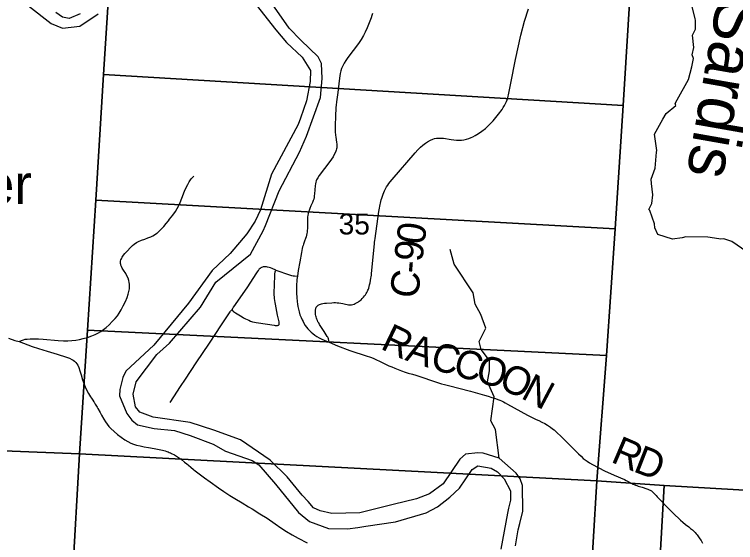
# Model space of a CAD drawing. Extents: x 396.2 to 468.4, y 232.6 to 279.1.
# Drawn here: x 421.615 to 423.054, y 274.071 to 275.126 of the extents above; entities that cross this region are included whole.
import ezdxf

# ---------------------------------------------------------------- set-up
doc = ezdxf.new("R2010")
doc.units = 0
for name, color, linetype in [('GM_X_County_Road', 7, 'Continuous'), ('GM_X_County_Road_Text', 7, 'Continuous'), ('GM_X_Major_River', 7, 'Continuous'), ('GM_X_Minor_River', 7, 'Continuous'), ('GM_X_Minor_River_Text', 7, 'Continuous'), ('GM_X_Section', 7, 'Continuous'), ('GM_X_Section_Text', 7, 'Continuous'), ('GM_X_Township_Road', 7, 'Continuous'), ('GM_X_Unincorporated_Text', 7, 'Continuous')]:
    doc.layers.add(name, color=color, linetype=linetype)

msp = doc.modelspace()

# ---------------------------------------------------------------- linework, layer by layer
at = {"layer": 'GM_X_County_Road'}
for points in [[(422.2429, 274.4712), (422.2422, 274.4755), (422.2419, 274.4771), (422.2416, 274.4784), (422.2411, 274.48), (422.2403, 274.4815), (422.2394, 274.483), (422.2329, 274.4926), (422.224, 274.5067), (422.2222, 274.5098), (422.2208, 274.5124), (422.2197, 274.5148), (422.2186, 274.5173), (422.2178, 274.5195), (422.2171, 274.522), (422.2165, 274.5244), (422.2161, 274.527), (422.2157, 274.5301), (422.2156, 274.533), (422.2156, 274.5349), (422.2159, 274.5367), (422.2162, 274.538), (422.2167, 274.5395), (422.2175, 274.5411), (422.2185, 274.5425), (422.2198, 274.5439), (422.2214, 274.5452), (422.2225, 274.5459), (422.2238, 274.5465), (422.2257, 274.5473), (422.2281, 274.548), (422.2306, 274.5486), (422.234, 274.5491), (422.2376, 274.5493), (422.2487, 274.5503), (422.2526, 274.5505), (422.2557, 274.5505), (422.259, 274.5503), (422.2626, 274.5499), (422.2665, 274.5492), (422.2706, 274.5484), (422.2756, 274.5474), (422.2789, 274.5468), (422.2819, 274.5463), (422.2849, 274.5461), (422.2874, 274.5463), (422.2903, 274.5467), (422.2928, 274.5475), (422.2951, 274.5484), (422.2978, 274.5497), (422.3001, 274.5511), (422.3017, 274.5523), (422.3032, 274.5534), (422.3047, 274.5546), (422.3067, 274.5563), (422.3087, 274.5584), (422.3115, 274.5612), (422.3137, 274.5637), (422.3154, 274.5659), (422.3171, 274.5684), (422.3185, 274.5709), (422.3195, 274.573), (422.3205, 274.5753), (422.3213, 274.5773), (422.322, 274.5796), (422.3228, 274.5824), (422.3237, 274.5858), (422.3248, 274.5902), (422.3256, 274.5943), (422.3265, 274.5994), (422.327, 274.6021), (422.3274, 274.6052), (422.3277, 274.6086), (422.3334, 274.6675), (422.3338, 274.6712), (422.3342, 274.6743), (422.3347, 274.6782), (422.3425, 274.7324), (422.3435, 274.7393), (422.3442, 274.7433), (422.3448, 274.7466), (422.3454, 274.7493), (422.3462, 274.7524), (422.3471, 274.7554), (422.3484, 274.7592), (422.3497, 274.7632), (422.351, 274.767), (422.3523, 274.7705), (422.3536, 274.7738), (422.3554, 274.7774), (422.3577, 274.7813), (422.3599, 274.7849), (422.3622, 274.7882), (422.3651, 274.7919), (422.3686, 274.7961), (422.415, 274.8497), (422.42, 274.8555), (422.4251, 274.8605), (422.4301, 274.865), (422.435, 274.8687), (422.4396, 274.8717), (422.445, 274.8746), (422.45, 274.8768), (422.4535, 274.8779), (422.457, 274.8787), (422.4613, 274.8791), (422.4655, 274.879), (422.471, 274.8785), (422.4865, 274.8759), (422.492, 274.8753), (422.4975, 274.8748), (422.5024, 274.8748), (422.5073, 274.875), (422.5117, 274.8755), (422.517, 274.8766), (422.5218, 274.878), (422.5263, 274.8798), (422.5298, 274.8813), (422.5341, 274.8838), (422.541, 274.888), (422.5476, 274.8926), (422.5549, 274.8983), (422.5605, 274.9032), (422.5653, 274.9079), (422.5703, 274.9135), (422.5811, 274.9268), (422.588, 274.9363), (422.5904, 274.9402), (422.5928, 274.9443), (422.5949, 274.9482), (422.5967, 274.9518), (422.5981, 274.9554), (422.5993, 274.9591), (422.6003, 274.9627), (422.601, 274.9655), (422.6057, 274.9883), (422.6151, 275.0357), (422.6257, 275.0841), (422.6329, 275.1122), (422.6405, 275.1367)], [(422.3296, 275.128), (422.3283, 275.1239), (422.3267, 275.1189), (422.3187, 275.0988), (422.3149, 275.0905), (422.3116, 275.0837), (422.3068, 275.0756), (422.3018, 275.0679), (422.2805, 275.0397), (422.2764, 275.0338), (422.273, 275.0282), (422.2703, 275.0233), (422.2678, 275.018), (422.2662, 275.0132), (422.2649, 275.0077), (422.2642, 275.0031), (422.2635, 274.9984), (422.2606, 274.9697), (422.2579, 274.9511), (422.2572, 274.9449), (422.2567, 274.94), (422.2563, 274.934), (422.256, 274.9279), (422.255, 274.8986), (422.2552, 274.8912), (422.2556, 274.885), (422.2562, 274.8805), (422.257, 274.8758), (422.258, 274.8701), (422.2582, 274.8674), (422.2584, 274.865), (422.2584, 274.8625), (422.2582, 274.8598), (422.2578, 274.8574), (422.2571, 274.8548), (422.2555, 274.8506), (422.2533, 274.8461), (422.2509, 274.8416), (422.2481, 274.837), (422.2445, 274.8319), (422.2232, 274.8045), (422.2203, 274.7999), (422.219, 274.7976), (422.2181, 274.7955), (422.2172, 274.7934), (422.2165, 274.791), (422.2158, 274.7874), (422.2154, 274.7835), (422.2147, 274.7756), (422.2139, 274.7675), (422.2135, 274.7638), (422.213, 274.7605), (422.2123, 274.7573), (422.2112, 274.7541), (422.2098, 274.7506), (422.2068, 274.7436), (422.2047, 274.7384), (422.2032, 274.7347), (422.2021, 274.7314), (422.2011, 274.728), (422.2005, 274.7248), (422.2001, 274.7208), (422.1999, 274.7167), (422.1998, 274.7077), (422.1996, 274.6986), (422.1994, 274.6945), (422.1991, 274.6912), (422.1987, 274.6885), (422.198, 274.6854), (422.1971, 274.6821), (422.196, 274.6788), (422.194, 274.673), (422.1919, 274.6671), (422.191, 274.6644), (422.1902, 274.6615), (422.1894, 274.6583), (422.1887, 274.6547), (422.1879, 274.6506), (422.1845, 274.6322), (422.1816, 274.6146), (422.1798, 274.6032), (422.1788, 274.5966), (422.1784, 274.5922), (422.178, 274.5879), (422.1779, 274.584), (422.1779, 274.5798), (422.178, 274.5751), (422.1782, 274.5693), (422.1788, 274.5608), (422.1795, 274.553), (422.1802, 274.5475), (422.1809, 274.5429), (422.1818, 274.5377), (422.1832, 274.5319), (422.1849, 274.5262), (422.1871, 274.5206), (422.1892, 274.5162), (422.191, 274.5126), (422.1929, 274.5092), (422.1954, 274.5051), (422.1981, 274.5013), (422.2006, 274.4982), (422.204, 274.4945), (422.207, 274.4916), (422.2104, 274.4886), (422.2145, 274.4852), (422.2186, 274.4825), (422.2229, 274.4801), (422.2274, 274.478), (422.2342, 274.4749), (422.2429, 274.4712), (422.2598, 274.4645), (422.2845, 274.4548), (422.319, 274.4435), (422.3236, 274.4421), (422.3278, 274.4406), (422.3324, 274.4388), (422.3376, 274.4365), (422.3433, 274.4338), (422.3499, 274.4305), (422.3624, 274.4245), (422.3681, 274.422), (422.3741, 274.4195), (422.3876, 274.4144), (422.3946, 274.4119), (422.401, 274.4099), (422.4093, 274.4075), (422.416, 274.4055), (422.461, 274.3905), (422.4675, 274.3885), (422.4735, 274.3868), (422.4815, 274.3847), (422.5253, 274.3734), (422.5531, 274.3657), (422.5605, 274.3635), (422.5679, 274.3611), (422.5748, 274.3589), (422.5796, 274.3571), (422.5836, 274.3555), (422.5871, 274.3541), (422.5909, 274.3522), (422.5945, 274.3503), (422.5992, 274.3475), (422.6386, 274.3258), (422.6558, 274.3173), (422.6612, 274.3149), (422.6674, 274.3121), (422.6735, 274.309), (422.6789, 274.3059), (422.6846, 274.3021), (422.689, 274.2986), (422.6919, 274.2962), (422.6947, 274.2937), (422.6987, 274.2899), (422.7047, 274.2844), (422.7226, 274.2663), (422.7409, 274.2483), (422.7457, 274.2436), (422.7502, 274.2395), (422.754, 274.2365), (422.758, 274.2338), (422.7627, 274.2308), (422.7684, 274.2274), (422.7924, 274.2149), (422.8119, 274.2057), (422.8324, 274.197), (422.836, 274.1953), (422.8398, 274.1933), (422.8492, 274.1883), (422.8518, 274.1872), (422.8543, 274.1862), (422.857, 274.1852), (422.8597, 274.1843), (422.8677, 274.1817), (422.8769, 274.1788), (422.8792, 274.178), (422.8816, 274.177), (422.8838, 274.1759), (422.8859, 274.1744), (422.888, 274.1728), (422.8904, 274.1706), (422.8928, 274.1682), (422.8954, 274.1655), (422.8978, 274.1629), (422.9027, 274.1573), (422.9193, 274.14), (422.9294, 274.1298), (422.9442, 274.1159), (422.9485, 274.1121), (422.9542, 274.1073), (422.9605, 274.1025), (422.9641, 274.0998), (422.9678, 274.0969), (422.9709, 274.0942), (422.9734, 274.0916), (422.9755, 274.0891), (422.9776, 274.0866), (422.9829, 274.0791), (422.985, 274.0758), (422.9868, 274.0726), (422.9883, 274.0699)], [(421.6036, 274.4796), (421.6158, 274.4751), (421.6249, 274.4725), (421.642, 274.466), (421.6508, 274.4629), (421.6632, 274.4588), (421.6804, 274.4535), (421.7007, 274.4477), (421.719, 274.4417), (421.7249, 274.4396), (421.7299, 274.4372), (421.7325, 274.4356), (421.7349, 274.4337), (421.7375, 274.431), (421.7394, 274.4285), (421.7414, 274.4253), (421.7435, 274.4209), (421.7459, 274.4145), (421.7484, 274.4061), (421.7512, 274.396), (421.754, 274.3877), (421.7563, 274.382), (421.7589, 274.3764), (421.7628, 274.3693), (421.7671, 274.3626), (421.7687, 274.36), (421.7718, 274.3556), (421.7736, 274.3525), (421.7743, 274.3515), (421.7766, 274.3478), (421.78, 274.342), (421.7811, 274.3401), (421.7818, 274.3389), (421.7862, 274.331), (421.7891, 274.3257), (421.7935, 274.3175), (421.7967, 274.3122), (421.7999, 274.3077), (421.8035, 274.3034), (421.8078, 274.2989), (421.8142, 274.293), (421.8208, 274.2873), (421.8281, 274.2817), (421.8353, 274.2767), (421.8416, 274.2729), (421.8471, 274.2701), (421.8527, 274.2677), (421.8586, 274.2659), (421.8658, 274.2642), (421.8742, 274.2626), (421.8828, 274.2612), (421.8938, 274.2593), (421.9042, 274.2574), (421.9109, 274.2559), (421.9156, 274.2546), (421.9191, 274.2534), (421.922, 274.2523), (421.9242, 274.2514), (421.9265, 274.2504), (421.9286, 274.2494), (421.9346, 274.2463), (421.9383, 274.2441), (421.9425, 274.2414), (421.9485, 274.237), (421.9548, 274.232), (421.959, 274.2284), (421.9623, 274.2256), (421.9671, 274.2216), (421.9723, 274.2173), (421.9758, 274.2147), (421.9837, 274.2086), (421.9892, 274.2045), (421.9941, 274.2008), (422.0057, 274.1924), (422.0224, 274.1806), (422.0332, 274.1733), (422.0451, 274.1654), (422.0546, 274.1595), (422.0695, 274.1506), (422.0824, 274.143), (422.0898, 274.1385), (422.1051, 274.129), (422.1192, 274.1199), (422.1351, 274.1091), (422.1469, 274.101), (422.1583, 274.0935), (422.169, 274.0871), (422.1814, 274.0801), (422.199, 274.0709)]]:
    msp.add_lwpolyline(points, dxfattribs=at)
at = {"layer": 'GM_X_Major_River'}
for points in [[(422.0657, 275.186), (422.1369, 275.0954), (422.1582, 275.0697), (422.189, 275.0407), (422.2058, 275.0138), (422.2055, 274.9918), (422.1982, 274.9531), (422.1859, 274.9185), (422.181, 274.9063), (422.1279, 274.807), (422.1059, 274.7356), (422.0958, 274.7131), (422.0786, 274.6876), (422.0459, 274.6483), (422.0098, 274.6144), (421.9628, 274.5496), (421.893, 274.4657), (421.8376, 274.4138), (421.8313, 274.4009), (421.8254, 274.3773), (421.8251, 274.3644), (421.8396, 274.3288), (421.8495, 274.3156), (421.8609, 274.3066), (421.8939, 274.2988), (421.9344, 274.2952), (421.9658, 274.2852), (422.012, 274.268), (422.0363, 274.2541), (422.0894, 274.2355), (422.1026, 274.2264), (422.1361, 274.1883), (422.1818, 274.1317), (422.2042, 274.1132), (422.2418, 274.0994), (422.2796, 274.0985), (422.3004, 274.1016), (422.3162, 274.104), (422.3752, 274.1131), (422.4364, 274.1309), (422.4594, 274.1424), (422.4838, 274.1619), (422.503, 274.1802), (422.5285, 274.2176), (422.5395, 274.2244), (422.5664, 274.2197), (422.5793, 274.2125), (422.5926, 274.1986), (422.6048, 274.1748), (422.6049, 274.1558), (422.6012, 274.1402), (422.599, 274.13), (422.5858, 274.0582)], [(421.6434, 275.1429), (421.6886, 275.1075), (421.7114, 275.0982), (421.7454, 275.1026), (421.782, 275.1267)], [(422.6152, 274.0648), (422.6203, 274.0971), (422.6237, 274.1092), (422.6296, 274.1339), (422.6286, 274.1851), (422.624, 274.1988), (422.6163, 274.2097), (422.5825, 274.2399), (422.5503, 274.2499), (422.5397, 274.2506), (422.5151, 274.2478), (422.5035, 274.2379), (422.4708, 274.1888), (422.4433, 274.1689), (422.4177, 274.1589), (422.3708, 274.1472), (422.304, 274.1305), (422.2484, 274.1294), (422.2249, 274.1346), (422.2117, 274.141), (422.2014, 274.1534), (422.1892, 274.1662), (422.1591, 274.2025), (422.1253, 274.2357), (422.0664, 274.2763), (422.013, 274.2957), (421.966, 274.3114), (421.8919, 274.3215), (421.8653, 274.3316), (421.8566, 274.3426), (421.8523, 274.368), (421.8582, 274.3923), (421.8995, 274.4472), (421.9243, 274.4693), (421.9867, 274.5414), (422.0167, 274.5913), (422.086, 274.647), (422.1115, 274.6939), (422.1159, 274.7045), (422.1435, 274.7737), (422.184, 274.8506), (422.1978, 274.8829), (422.2257, 274.9601), (422.2293, 274.998), (422.228, 275.0276), (422.2211, 275.0412), (422.1865, 275.0744), (422.1633, 275.0982), (422.1248, 275.1534)], [(421.7464, 275.1272), (421.7241, 275.1176), (421.7113, 275.1206), (421.698, 275.1296)]]:
    msp.add_lwpolyline(points, dxfattribs=at)
at = {"layer": 'GM_X_Minor_River'}
for points in [[(423.0767, 274.6521), (423.0465, 274.6726), (423.0306, 274.6779), (423.0242, 274.6771), (423.0207, 274.6779), (422.9984, 274.6812), (422.9546, 274.6819), (422.9474, 274.6796), (422.9281, 274.6773), (422.899, 274.6867), (422.8926, 274.6996), (422.8922, 274.708), (422.8827, 274.7342), (422.8808, 274.7364), (422.8869, 274.7486), (422.8887, 274.7654), (422.8864, 274.7885), (422.8857, 274.7969), (422.8936, 274.819), (422.8962, 274.8509), (422.8966, 274.8543), (422.8924, 274.887), (422.9086, 274.9167), (422.9154, 274.9281), (422.9347, 274.9437), (422.9335, 274.9483), (422.9377, 274.9551), (422.9603, 274.9959), (422.9664, 275.021), (422.9701, 275.0381), (422.9675, 275.0449), (422.9705, 275.0597), (422.9682, 275.0844), (422.9739, 275.0962), (422.9742, 275.1145), (422.9735, 275.1171), (422.964, 275.1555)], [(422.5825, 274.2399), (422.5748, 274.2968), (422.5655, 274.3142), (422.5722, 274.3622), (422.5591, 274.3926), (422.5628, 274.4142), (422.5627, 274.4347), (422.5467, 274.4568), (422.5427, 274.4729), (422.5556, 274.4995), (422.5458, 274.5267), (422.5347, 274.5476), (422.5305, 274.5701), (422.4922, 274.6272), (422.4847, 274.6563)]]:
    msp.add_lwpolyline(points, dxfattribs=at)
at = {"layer": 'GM_X_Section'}
for points in [[(420.7452, 275.2968), (421.8081, 275.2441), (421.7928, 275.0058), (421.7775, 274.755), (421.761, 274.4956), (421.7452, 274.2485), (420.6845, 274.2907)], [(421.8083, 275.2473), (422.8451, 275.1916), (422.8297, 274.9443), (421.7928, 275.0058), (421.8081, 275.2441)], [(423.0776, 275.1782), (423.8389, 275.1375), (423.8717, 275.1139), (423.872, 275.1138), (423.8759, 275.057), (423.8677, 275.0293), (423.8062, 274.1333), (422.9116, 274.1851), (422.7773, 274.1944), (422.7965, 274.4451), (422.8136, 274.6978), (422.8297, 274.9443), (422.8451, 275.1916)], [(422.8297, 274.9443), (422.8136, 274.6978), (421.7775, 274.755), (421.7928, 275.0058)], [(421.7775, 274.755), (422.8136, 274.6978), (422.7965, 274.4451), (421.761, 274.4956)], [(422.7965, 274.4451), (422.7773, 274.1944), (421.7452, 274.2485), (421.761, 274.4956)], [(421.7452, 274.2485), (421.7308, 274.0039), (421.7144, 273.7468), (421.6978, 273.4943), (421.682, 273.2458), (420.6294, 273.296), (420.6297, 273.3021), (420.6398, 273.4786), (420.6634, 273.8917), (420.6845, 274.2907)], [(422.7773, 274.1944), (422.7625, 273.9495), (421.7308, 274.0039), (421.7452, 274.2485)], [(422.7773, 274.1944), (422.9116, 274.1851), (422.9033, 274.0442), (422.8955, 273.9099), (422.888, 273.7823), (422.8811, 273.6643), (422.8741, 273.5445), (422.8674, 273.4297), (422.8607, 273.3162), (422.8528, 273.1802), (422.7149, 273.188), (422.7307, 273.4397), (422.7469, 273.6994), (422.7625, 273.9495)], [(422.9116, 274.1851), (423.8062, 274.1333), (423.7981, 273.9932), (422.9033, 274.0442)]]:
    msp.add_lwpolyline(points, close=True, dxfattribs=at)
at = {"layer": 'GM_X_Township_Road'}
for points in [[(421.6249, 274.4725), (421.6294, 274.4745), (421.631, 274.4754), (421.6333, 274.4764), (421.6363, 274.4772), (421.6406, 274.4777), (421.6467, 274.4781), (421.6536, 274.4784), (421.6629, 274.4782), (421.6728, 274.4776), (421.7025, 274.475), (421.713, 274.4743), (421.7217, 274.4742), (421.7298, 274.4746), (421.7378, 274.4756), (421.7452, 274.4768), (421.7524, 274.4785), (421.7608, 274.4809), (421.7696, 274.484), (421.7765, 274.4868), (421.7826, 274.4899), (421.7879, 274.4931), (421.793, 274.4967), (421.7983, 274.5009), (421.8043, 274.5063), (421.8105, 274.5125), (421.8159, 274.5185), (421.8205, 274.5243), (421.8241, 274.5294), (421.8283, 274.5363), (421.8324, 274.5439), (421.8367, 274.5529), (421.8398, 274.5604), (421.8422, 274.5674), (421.8436, 274.5728), (421.8446, 274.5777), (421.8449, 274.5827), (421.8448, 274.587), (421.8444, 274.5907), (421.8435, 274.5949), (421.8419, 274.5996), (421.8397, 274.6041), (421.8372, 274.6084), (421.8327, 274.6151), (421.8301, 274.6194), (421.8285, 274.6227), (421.8277, 274.6251), (421.8273, 274.6268), (421.827, 274.6285), (421.8269, 274.6298), (421.8269, 274.6312), (421.8271, 274.633), (421.8278, 274.636), (421.8286, 274.6382), (421.8294, 274.6401), (421.83, 274.6411), (421.8328, 274.6452), (421.8355, 274.6486), (421.8379, 274.6514), (421.8405, 274.6541), (421.8459, 274.6599), (421.8508, 274.6645), (421.8541, 274.6672), (421.8587, 274.6702), (421.863, 274.6725), (421.8687, 274.6749), (421.8751, 274.6772), (421.8815, 274.6795), (421.8873, 274.6818), (421.8912, 274.6837), (421.8965, 274.6868), (421.8995, 274.689), (421.9005, 274.6898), (421.9046, 274.6936), (421.9089, 274.698), (421.913, 274.7027), (421.9178, 274.7083), (421.9226, 274.714), (421.9249, 274.7169), (421.931, 274.7248), (421.9363, 274.7324), (421.9399, 274.7382), (421.943, 274.7443), (421.9458, 274.7505), (421.9492, 274.7591), (421.9546, 274.773), (421.9584, 274.7815), (421.9609, 274.7864), (421.9641, 274.7918), (421.9681, 274.7973), (421.9728, 274.8027)], [(422.137, 274.6154), (422.1291, 274.6185), (422.126, 274.6197), (422.1233, 274.6207), (422.1204, 274.6215), (422.1179, 274.622), (422.1155, 274.6222), (422.1137, 274.6222), (422.1117, 274.6219), (422.1099, 274.6213), (422.1081, 274.6205), (422.1066, 274.6197), (422.1052, 274.6186), (422.1038, 274.6174), (422.1025, 274.6159), (422.1013, 274.6145), (422.0995, 274.612), (422.0983, 274.6101), (422.0786, 274.5801), (422.0524, 274.5422), (422.0519, 274.5415), (422.0514, 274.5408), (422.0509, 274.5397), (422.0504, 274.5387), (422.0502, 274.5381), (422.0499, 274.5374), (422.0498, 274.5364)], [(422.1359, 274.5471), (422.1352, 274.551), (422.1346, 274.5547), (422.1341, 274.5589), (422.1338, 274.5622), (422.1337, 274.5653), (422.1337, 274.5692), (422.1345, 274.6036), (422.1346, 274.6053), (422.1347, 274.6069), (422.1348, 274.6082), (422.135, 274.6095), (422.1352, 274.6106), (422.1356, 274.6119), (422.137, 274.6154), (422.164, 274.6056), (422.1678, 274.6045), (422.1711, 274.604), (422.174, 274.6036), (422.1798, 274.6032)], [(422.1437, 274.5089), (422.1435, 274.51), (422.1431, 274.5121), (422.1398, 274.5254), (422.1359, 274.5471)], [(421.9257, 274.3511), (421.9331, 274.3625), (421.9466, 274.3833), (421.9563, 274.3979), (421.9775, 274.4303), (422.0044, 274.4698), (422.0283, 274.5058), (422.0456, 274.532), (422.0465, 274.5334), (422.0473, 274.5344), (422.0483, 274.5353), (422.0498, 274.5364)], [(422.0498, 274.5364), (422.05, 274.5351), (422.0504, 274.5341), (422.0513, 274.5333), (422.0525, 274.5325), (422.056, 274.5303), (422.0695, 274.522), (422.0725, 274.5204), (422.0761, 274.5184), (422.0797, 274.5166), (422.0828, 274.5152), (422.0862, 274.5137), (422.0899, 274.5124), (422.0939, 274.5113), (422.0977, 274.5107), (422.1023, 274.5099), (422.1332, 274.5053), (422.1355, 274.505), (422.1378, 274.5048), (422.1388, 274.5048), (422.14, 274.5049), (422.1413, 274.5052), (422.1421, 274.5056), (422.1427, 274.5061), (422.1433, 274.5069), (422.1436, 274.5078), (422.1437, 274.5089)]]:
    msp.add_lwpolyline(points, dxfattribs=at)

# ---------------------------------------------------------------- texts
at = {"layer": 'GM_X_County_Road_Text'}
for s, rotation, p in [('0', 81.9542, (422.4328, 274.6646)), ('9', 83.35, (422.4288, 274.6302)), ('-', 85.3252, (422.427, 274.6074)), ('C', 80.4007, (422.4185, 274.5561)), ('R', 334.3985, (422.3435, 274.4593)), ('A', 341.6318, (422.3928, 274.4362)), ('C', 343.3917, (422.4421, 274.4198)), ('C', 344.3882, (422.4878, 274.4062)), ('O', 344.246, (422.5327, 274.3937)), ('O', 335.6429, (422.5787, 274.3809)), ('N', 332.0469, (422.6235, 274.3607)), ('R', 336.9157, (422.803, 274.2332)), ('D', 338.667, (422.8477, 274.2142))]:
    msp.add_text(s, height=0.0568, rotation=rotation, dxfattribs=at).set_placement(p)
at = {"layer": 'GM_X_Minor_River_Text'}
msp.add_text('Sardis', height=0.0947, rotation=259.9987, dxfattribs=at).set_placement((423.0185, 275.1611))
at = {"layer": 'GM_X_Section_Text'}
msp.add_text('35', height=0.04186, rotation=0, dxfattribs=at).set_placement((422.2621, 274.6865))
at = {"layer": 'GM_X_Unincorporated_Text'}
msp.add_text('Thivener', height=0.07898, rotation=0, dxfattribs=at).set_placement((421.2392, 274.7472))

doc.saveas('drawing.dxf')
